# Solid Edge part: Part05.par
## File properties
Author: Robert a Rhodes jr
Template: Normal.par
Last saved by: CADCIM
Revision: 3
Application: Solid Edge
Accuracy: 0.99
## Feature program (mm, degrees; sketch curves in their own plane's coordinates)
body "unnamed Body 1"
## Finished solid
Body 1: solid body, 82 faces, 169 edges, 90 vertices.
  Faces by surface: cylinder 44, plane 27, torus 6, spline 3, cone 2
  Edges by curve: circle 64, ellipse 44, line 26, intersection 24, curve on surface 11
Bounding box of the edges (mm; curved faces can reach further): 3403.600 x 1854.200 x 1930.410, from (-1701.8, 0, -965.2014) to (1701.8, 1854.2, 965.2088).
Cylindrical faces by radius (mm): R63.5 x26, R76.2 x4, R95.25 x4, R317.5 x4, R342.9 x3, R558.8 x1, R965.2 x2
Conical faces (half-angle, radius in mm at the cone's reference point): 15 deg R654.5026 x1, 16.46 deg R711.4955 x1
Toroidal faces (ring radius, tube radius in mm): R408.1559 r101.6 x1, R609.6 r50.8 x1, R851.7802 r50.8 x1, R889 r76.2 x2, R983.9044 r127 x1
Planar faces by outward normal: +y 20, +z 1, -y 5, -z 1
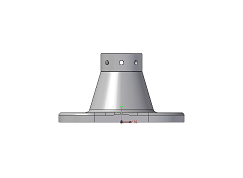
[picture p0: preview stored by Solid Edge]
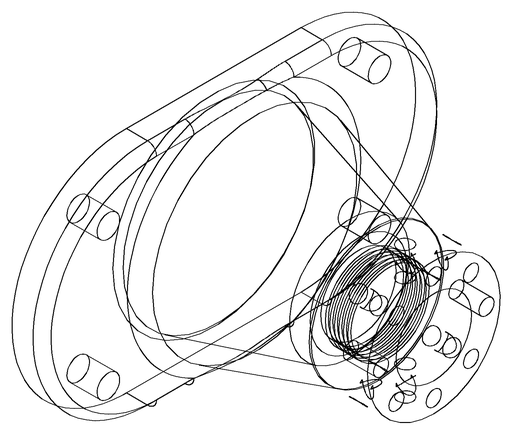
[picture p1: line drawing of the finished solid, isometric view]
